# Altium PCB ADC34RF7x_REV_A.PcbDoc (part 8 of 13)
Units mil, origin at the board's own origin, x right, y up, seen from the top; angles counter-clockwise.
Board outline 6250 x 2716.54 mil, 18 copper layers (Top Layer, L2 GND, L3 PWR, L4 GND, L5 PWR/SIG, L6 GND, L7 SIGNAL, L8 GND, L9 GND, L10 SIGNAL, L11 GND, L12 SIGNAL, L13 GND, L14 PWR, L15 GND, L16 PWR/SIG, L16 GND, Bottom Layer), stack 95.314 mil thick; 668 components, 786 nets, 3150 pads, 2020 vias.
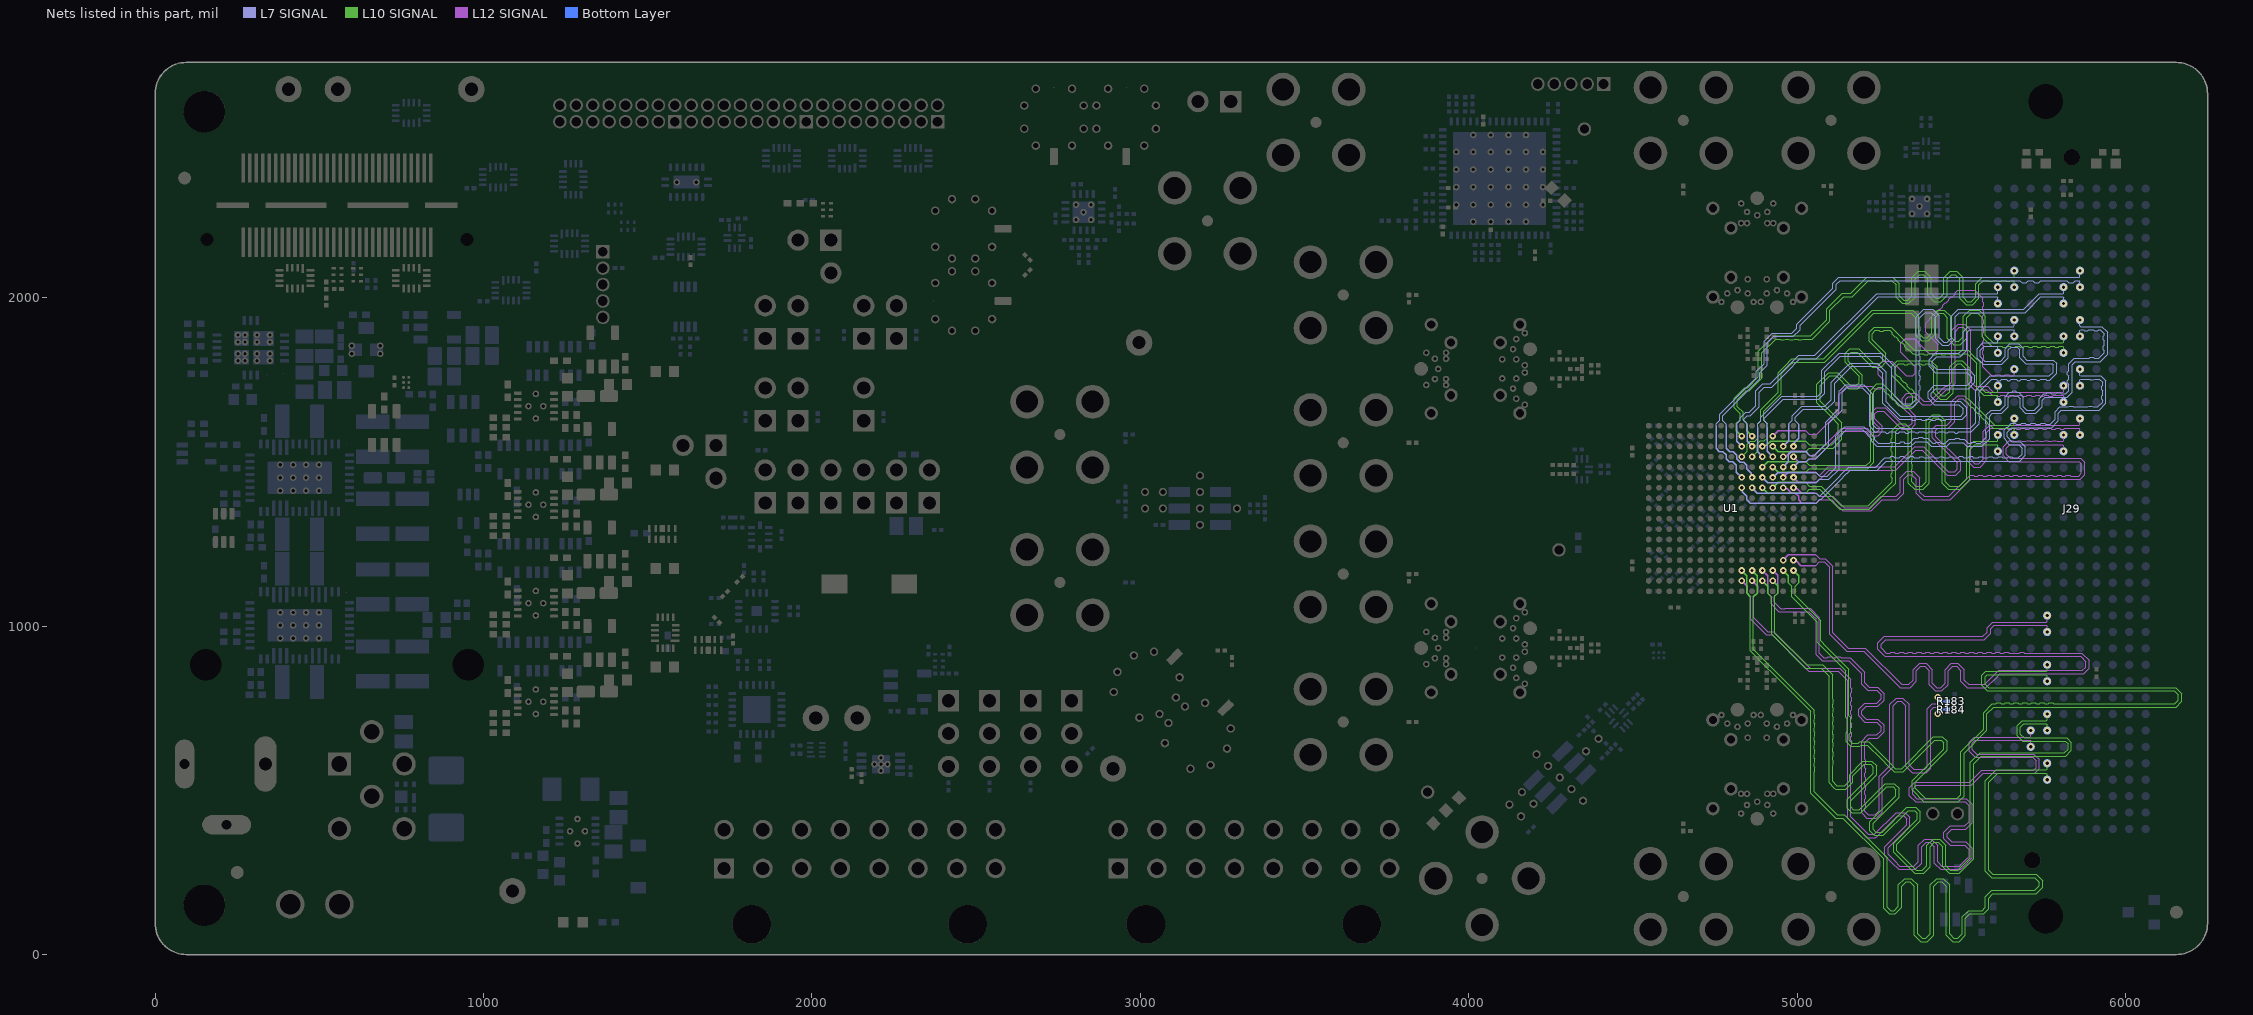
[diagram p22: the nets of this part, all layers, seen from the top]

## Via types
v1: diameter 20, hole 10, Top Layer to Bottom Layer, tented both sides, 1793 vias
v2: diameter 24, hole 12, Top Layer to Bottom Layer, tented both sides, 168 vias
v3: diameter 18, hole 8, Top Layer to Bottom Layer, tented both sides, 59 vias

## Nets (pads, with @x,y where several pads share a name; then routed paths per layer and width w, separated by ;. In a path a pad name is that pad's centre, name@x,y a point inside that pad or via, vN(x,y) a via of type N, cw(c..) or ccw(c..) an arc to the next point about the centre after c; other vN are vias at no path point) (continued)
LVDSA10_N: J29.G28 U1.C14 | length 2688
  L12 SIGNAL w3.5: 5056.71,1184.29 5068.06,1195.65 5081.98,1195.65 5099.03,1178.6 5099.03,975.58 5145.45,929.16 5151.3,923.31 5203.52,923.31 5314.56,812.27 5335.32,812.27 5344.14,812.27 5363.48,831.6 5363.48,863.69 5376.95,877.16 5388.5,877.16 5401.98,863.69 5401.98,821.92 5421.31,802.58 5441.14,802.58 5460.48,821.92 5460.48,863.69 5473.95,877.16 5485.5,877.16 5498.98,863.69 5498.98,831.6 5518.31,812.27 5564.85,812.27 5575.05,812.27 5605.9,843.13 5617.78,855 5873.13,855 5882.4,864.27 5889.08,870.95 5889.08,895.63 5867.19,917.52 5692.35,917.52 5689.77,920.1 5679.04,920.1 5676.46,917.52 5645.31,917.52 5642.73,920.1 5631.99,920.1 5629.41,917.52 5618.67,917.52 5616.09,920.1 5605.35,920.1 5602.78,917.52 5592.04,917.52 5589.46,920.1 5578.72,920.1 5576.14,917.52 5565.4,917.52 5562.82,920.1 5552.08,920.1 5549.5,917.52 5538.77,917.52 5536.19,920.1 5525.45,920.1 5522.87,917.52 5512.13,917.52 5509.55,920.1 5498.81,920.1 5496.23,917.52 5485.49,917.52 5482.91,920.1 5472.18,920.1 5469.6,917.52 5458.86,917.52 5456.28,920.1 5445.54,920.1 5442.96,917.52 5432.22,917.52 5429.64,920.1 5418.91,920.1 5416.33,917.52 5405.59,917.52 5403.01,920.1 5392.27,920.1 5389.69,917.52 5378.95,917.52 5376.37,920.1 5365.63,920.1 5363.05,917.52 5352.32,917.52 5349.74,920.1 5339,920.1 5336.42,917.52 5325.68,917.52 5323.1,920.1 5312.36,920.1 5309.78,917.52 5299.05,917.52 5296.47,920.1 5285.73,920.1 5283.15,917.52 5272.41,917.52 ; 5272.19,917.52 5256.15,933.55 5256.15,945.1 5269.63,958.58 5569.75,958.58 5589.08,977.91 5589.08,991.3 5595.45,997.68 5600.05,1002.27 5759.37,1002.27 5761.42,1000.22 v1(5761.42,982.27)
  L12 SIGNAL w4: v1(4988.98,1200.76) 4992.04,1197.7 4998.27,1197.7 5011.69,1184.29 5056.71,1184.29
LVDSA10_P: J29.G27 U1.D14 | length 2687.6
  L12 SIGNAL w3.5: 5056.95,1217 5068.3,1205.65 5086.12,1205.65 5109.03,1182.74 5109.03,979.72 5155.45,933.31 5207.66,933.31 5318.7,822.27 5335.32,822.27 5340,822.27 5353.48,835.74 5353.48,867.83 5372.81,887.16 5392.64,887.16 5411.98,867.83 5411.98,826.06 5425.45,812.58 5437,812.58 5450.48,826.06 5450.48,867.83 5469.81,887.16 5489.64,887.16 5508.98,867.83 5508.98,835.74 5522.45,822.27 5564.85,822.27 5570.9,822.27 5595.9,847.27 5613.64,865 5868.99,865 5878.26,874.27 5879.08,875.09 5879.08,891.49 5863.05,907.52 5268.05,907.52 5265.12,910.45 5246.15,929.41 5246.15,949.24 5265.49,968.58 5565.61,968.58 5579.08,982.05 5579.08,995.44 5595.9,1012.27 5759.37,1012.27 5761.42,1014.32 v1(5761.42,1032.27)
  L12 SIGNAL w4: v1(4957.48,1200.76) 4973.72,1217 5056.95,1217
LVDSA11_N: J29.G36 U1.G15 | length 3070.6
  L10 SIGNAL w3.5: 4866.98,1089.08 4866.73,1088.83 4866.73,929.01 4910.73,885.01 5051.52,744.22 5051.52,731.49 5054.1,728.91 5054.1,718.17 5051.52,715.59 5051.52,704.85 5054.1,702.27 5054.1,691.53 5051.52,688.95 5051.52,678.21 5054.1,675.63 5054.1,664.9 5051.52,662.32 5051.52,651.58 5054.1,649 5054.1,638.26 5051.52,635.68 5051.52,624.94 5054.1,622.36 5054.1,611.62 5051.52,609.04 5051.52,598.31 5054.1,595.73 5054.1,584.99 5051.52,582.41 5051.52,571.67 5054.1,569.09 5054.1,558.35 5051.52,555.77 5051.52,495.71 5121.71,425.52 5143.48,425.52 5273.93,295.07 5273.93,144.65 5284.67,133.9 5290.63,133.9 5295.31,133.9 5308.78,147.38 5308.78,212.07 5328.11,231.4 5347.95,231.4 5367.28,212.07 5367.28,62.67 5380.76,49.2 5392.31,49.2 5405.78,62.67 5405.78,212.07 5425.11,231.4 5444.95,231.4 5464.28,212.07 5464.28,62.67 5477.76,49.2 5489.31,49.2 5502.78,62.67 5502.78,114.57 5522.11,133.9 5556.49,133.9 5563.67,133.9 5573,143.23 5573,175.94 5592.33,195.27 5724.44,195.27 5737.91,208.74 5737.91,220.29 5724.44,233.77 5592.33,233.77 5573,253.1 5573,261.92 5573,529 5606.27,562.27 5759.37,562.27 5761.42,564.32 v1(5761.42,582.27)
  L10 SIGNAL w4: v1(4862.99,1169.29) 4878.51,1153.78 4878.51,1144.44 4878.49,1131.17 ; 4866.98,1089.08 4878.51,1100.6 4878.51,1131.15
LVDSA11_P: J29.G37 U1.H15 | length 3071.3
  L10 SIGNAL w3.5: 4856.48,1091.59 4856.73,1091.34 4856.73,924.87 4906.59,875.01 4922.41,859.19 4987.84,793.76 5041.52,740.08 5041.52,491.56 5117.57,415.52 5139.34,415.52 5263.93,290.93 5263.93,140.51 5280.53,123.9 5290.63,123.9 5299.45,123.9 5318.78,143.24 5318.78,207.93 5332.26,221.4 5343.81,221.4 5357.28,207.93 5357.28,58.53 5376.61,39.2 5396.45,39.2 5415.78,58.53 5415.78,207.93 5429.26,221.4 5440.81,221.4 5454.28,207.93 5454.28,58.53 5473.61,39.2 5493.45,39.2 5512.78,58.53 5512.78,110.43 5526.26,123.9 5556.49,123.9 5567.81,123.9 5583,139.09 5583,143.23 5583,171.79 5596.47,185.27 5728.58,185.27 5747.91,204.6 5747.91,224.44 5728.58,243.77 5596.47,243.77 5583,257.24 5583,261.92 5583,524.86 5610.41,552.27 5759.37,552.27 5761.42,550.22 v1(5761.42,532.27)
  L10 SIGNAL w4: v1(4831.5,1169.29) 4846.99,1153.8 4846.99,1101.09 4856.48,1091.59
LVDSA12_N: R183.2 U1.E15 | length 2135.8
  L12 SIGNAL w3.5: 4940.98,1100.09 4930.98,1090.09 4930.98,1072.11 4948.98,1054.11 4949.59,1054.11 4950.72,1052.98 4962.94,1052.98 4964.06,1054.11 5039.46,1054.11 5067.68,1025.88 5067.68,917.43 5080.82,904.29 5091.56,904.29 5094.14,906.87 5104.88,906.87 5107.46,904.29 5118.2,904.29 5120.78,906.87 5131.51,906.87 5134.09,904.29 5161.3,904.29 5203.52,862.07 5206.45,859.14 5206.45,832.27 5206.45,827.59 5219.92,814.11 5246.35,814.11 5265.68,794.78 5265.68,774.95 5246.35,755.61 5210.73,755.61 5197.25,742.14 5197.25,730.59 5210.73,717.11 5246.35,717.11 5265.68,697.78 5265.68,677.95 5246.35,658.61 5219.92,658.61 5206.45,645.14 5206.45,594.97 5209.03,592.39 5209.03,581.65 5206.45,579.07 5206.45,568.33 5209.03,565.75 5209.03,555.01 5206.45,552.43 5206.45,541.7 5209.03,539.12 5209.03,528.38 5206.45,525.8 5206.45,515.06 5209.03,512.48 5209.03,501.74 5206.45,499.16 5206.45,488.42 5209.03,485.84 5209.03,475.11 5206.45,472.53 5206.45,461.79 5209.03,459.21 5209.03,448.47 5206.45,445.89 5206.45,435.69 5216.63,425.52 5237.42,425.52 5250,438.09 5250,542.65 5264.52,557.18 5282.68,575.33 5282.68,761.49 5302.01,780.82 5321.85,780.82 5341.18,761.49 5341.18,577.34 5354.65,563.87 5361.88,563.87 5389.05,563.87 5396.37,571.19 5396.37,748 5411.6,763.24 5426,763.24 5428.05,765.29 v1(5428.05,783.24)
  L12 SIGNAL w4: v1(4925.98,1169.29) 4940.98,1154.29 4940.98,1100.09
  Bottom Layer w6.5: v1(5428.05,783.24) 5440.55,770.74 R183.2@5458.05,770.74
LVDSA12_P: R184.2 U1.F15 | length 2134.8
  L12 SIGNAL w3.5: 4910.98,1100.09 4920.98,1090.09 4920.98,1082.27 ; 4920.98,1082.03 4920.98,1067.97 4944.84,1044.11 4945.45,1044.11 4945.53,1044.03 4968.13,1044.03 4968.2,1044.11 5035.31,1044.11 5049.78,1029.64 5057.68,1021.74 5057.68,913.29 5076.68,894.29 5157.16,894.29 5196.45,855 5196.45,832.27 5196.45,823.45 5215.78,804.11 5242.2,804.11 5255.68,790.64 5255.68,779.09 5242.2,765.61 5206.58,765.61 5187.25,746.28 5187.25,726.45 5206.58,707.11 5242.2,707.11 5255.68,693.64 5255.68,682.09 5242.2,668.61 5215.78,668.61 5196.45,649.28 5196.45,594.97 5196.45,431.55 5212.48,415.52 5241.57,415.52 5260,433.95 5260,538.51 5264.52,543.04 5292.68,571.19 5292.68,757.35 5306.15,770.82 5317.7,770.82 5331.18,757.35 5331.18,573.2 5350.51,553.87 5361.88,553.87 5393.19,553.87 5406.37,567.05 5406.37,743.86 5415.75,753.24 5426,753.24 5428.05,751.19 v1(5428.05,733.24)
  L12 SIGNAL w4: v1(4894.49,1169.29) 4910.98,1152.8 4910.98,1106.3 4910.98,1100.09
  Bottom Layer w6.5: v1(5428.05,733.24) 5440.55,745.74 R184.2@5458.05,745.74
LVDSA13_N: J29.G30 U1.C15 | length 3101.8
  L10 SIGNAL w3.5: 5004.98,1132.09 4994.23,1121.34 4994.23,1093.7 5071.48,1016.45 5071.48,954.97 5087.45,939.01 5157.97,868.49 5157.97,727.14 5163.29,721.81 5163.29,675.12 5159.48,671.3 5159.48,652.24 5167.64,644.07 5186.7,644.07 5190.52,647.89 5217.86,647.89 5220.79,644.96 5286.73,579.02 5299.63,566.13 5318.68,566.13 5415.32,662.76 5442.66,662.76 5456.68,648.73 5456.68,621.39 5360.05,524.76 5360.05,505.7 5390.24,475.52 5487.23,475.52 5498.36,486.64 5498.36,616.97 5567.81,686.41 5567.81,736.73 5594.65,763.57 5605.38,763.57 5607.96,766.15 5618.7,766.15 5621.28,763.57 5632.02,763.57 5634.6,766.15 5645.34,766.15 5647.92,763.57 5658.66,763.57 5661.24,766.15 5671.97,766.15 5674.55,763.57 5685.29,763.57 5687.87,766.15 5698.61,766.15 5701.19,763.57 5711.93,763.57 5714.51,766.15 5725.24,766.15 5727.82,763.57 5738.56,763.57 5741.14,766.15 5751.88,766.15 5754.46,763.57 5765.2,763.57 5767.78,766.15 5778.52,766.15 5781.1,763.57 6149.83,763.57 6161,774.74 6161,790.51 6148.56,802.95 5579.45,802.95 5565.93,816.47 5563,819.4 5563,850.6 5574.67,862.27 5759.37,862.27 5761.42,864.32 v1(5761.42,882.27)
  L10 SIGNAL w4: v1(4988.98,1169.29) 5004.98,1153.29 5004.98,1132.09
LVDSA13_P: J29.G31 U1.D15 | length 3103.4
  L10 SIGNAL w3.5: 4973.48,1131.58 4984.23,1120.83 4984.23,1089.56 5061.48,1012.31 5061.48,950.83 5083.31,929.01 5147.97,864.35 5147.97,723 5153.29,717.67 5153.29,679.26 5149.48,675.44 5149.48,648.1 5163.5,634.07 5190.84,634.07 5194.66,637.89 5213.72,637.89 5254.25,597.36 5257.55,594.06 5276.73,574.88 5295.48,556.13 5322.82,556.13 5369.46,602.76 5419.46,652.76 5438.51,652.76 5446.68,644.59 5446.68,625.54 5396.68,575.54 5350.05,528.9 5350.05,501.56 5386.1,465.52 5491.38,465.52 5508.36,482.5 5508.36,612.82 5571.95,676.41 5577.81,682.27 5577.81,732.59 5598.79,753.57 6153.97,753.57 6171,770.6 6171,794.65 6152.7,812.95 5583.59,812.95 5573,823.54 5573,846.45 5578.81,852.27 5759.37,852.27 5761.42,850.22 v1(5761.42,832.27)
  L10 SIGNAL w4: v1(4957.48,1169.29) 4973.48,1153.29 4973.48,1131.58
LVDSA14_N: J29.H34 U1.G16 | length 3081.5
  L12 SIGNAL w3.5: 4879.49,1101.58 4868.74,1090.83 4868.74,1025.31 4910.76,983.29 4928.7,983.29 4934.56,977.43 5039.55,872.45 5129.35,872.45 5163.52,838.28 5163.52,812.27 5166.1,809.69 5166.1,798.95 5163.52,796.37 5163.52,785.63 5166.1,783.05 5166.1,772.32 5163.52,769.74 5163.52,759 5166.1,756.42 5166.1,745.68 5163.52,743.1 5163.52,732.36 5166.1,729.78 5166.1,719.04 5163.52,716.46 5163.52,705.73 5166.1,703.15 5166.1,692.41 5163.52,689.83 5163.52,679.09 5166.1,676.51 5166.1,665.77 5163.52,663.19 5163.52,652.45 5166.1,649.88 5166.1,639.14 5163.52,636.56 5163.52,418.9 5184.77,397.65 5213.32,369.1 5216.63,365.79 5235.68,365.79 5301.95,432.06 5329.29,432.06 5343.31,418.03 5343.31,390.69 5277.05,324.43 5277.05,305.37 5292.35,290.07 5295.66,286.76 5313.16,269.26 5350.98,269.26 5355.66,269.26 5369.13,282.73 5369.13,331.96 5388.46,351.3 5408.3,351.3 5427.63,331.96 5427.63,282.73 5441.11,269.26 5494.77,269.26 5500.38,274.86 5503.39,277.87 5520,294.48 5523.65,298.14 5523.65,314.81 5523.65,319.49 5510.18,332.97 5466.35,332.97 5447.02,352.3 5447.02,372.14 5466.35,391.47 5510.18,391.47 5523.65,404.94 5523.65,435.69 5523.65,452.73 5511.64,464.74 5360.91,464.74 5341.55,484.09 5341.55,507.48 5358.77,524.7 5525.86,524.7 5562.7,561.54 5719.8,561.54 5727.56,569.29 5727.56,589.73 5716.92,600.36 5542.46,600.36 5539.53,603.29 5523.65,619.17 5523.65,647.06 5538.86,662.27 5709.37,662.27 5711.42,664.32 v1(5711.42,682.27)
  L12 SIGNAL w4: v1(4862.99,1137.8) 4879.49,1121.3 4879.49,1101.58
LVDSA14_P: J29.H35 U1.H16 | length 3083.1
  L12 SIGNAL w3.5: 4847.99,1100.09 4858.74,1089.34 4858.74,1021.17 4872.42,1007.49 4906.62,973.29 4924.56,973.29 5035.41,862.45 5125.21,862.45 5153.52,834.14 5153.52,414.76 5180.63,387.65 5196.45,371.83 5206.25,362.03 5209.55,358.72 5212.48,355.79 5239.82,355.79 5306.09,422.06 5325.14,422.06 5333.31,413.89 5333.31,394.83 5267.05,328.57 5267.05,301.23 5285.28,282.99 5288.59,279.69 5309.02,259.26 5350.98,259.26 5359.8,259.26 5379.13,278.59 5379.13,327.82 5392.61,341.3 5404.16,341.3 5417.63,327.82 5417.63,278.59 5436.96,259.26 5498.92,259.26 5507.45,267.79 5518.25,278.59 5520,280.34 5533.65,293.99 5533.65,314.81 5533.65,323.64 5514.32,342.97 5470.49,342.97 5457.02,356.44 5457.02,367.99 5470.49,381.47 5514.32,381.47 5533.65,400.8 5533.65,435.69 5533.65,456.87 5515.78,474.74 5365.05,474.74 5351.55,488.23 5351.55,503.34 5362.92,514.7 5530,514.7 5566.84,551.54 5723.94,551.54 5737.56,565.15 5737.56,593.87 5723.99,607.43 5721.06,610.36 5546.6,610.36 5533.65,623.31 5533.65,642.92 5543,652.27 5709.37,652.27 5711.42,650.22 v1(5711.42,632.27)
  L12 SIGNAL w4: v1(4831.5,1137.8) 4847.99,1121.3 4847.99,1100.09
LVDSA15_N: J29.G33 U1.E16 | length 3112
  L10 SIGNAL w3.5: 4940.36,1099.46 4932.69,1091.79 4932.69,978.64 5029.06,882.27 5077.59,882.27 5108,851.86 5108,777.57 5110.58,774.99 5110.58,764.26 5108,761.68 5108,750.94 5110.58,748.36 5110.58,737.62 5108,735.04 5108,724.3 5110.58,721.72 5110.58,710.99 5108,708.41 5108,697.67 5110.58,695.09 5110.58,684.35 5108,681.77 5108,671.03 5110.58,668.45 5110.58,657.71 5108,655.13 5108,644.4 5110.58,641.82 5110.58,631.08 5108,628.5 5108,617.76 5110.58,615.18 5110.58,604.44 5108,601.86 5108,591.12 5110.58,588.55 5110.58,577.81 5108,575.23 5108,526.89 5117.92,516.98 5121.22,513.67 5144.43,513.67 5159.76,529 5159.76,544 5159.76,548.14 5200.48,588.87 5227.82,588.87 5241.85,574.84 5241.85,547.5 5162.79,468.45 5162.79,449.39 5170.96,441.22 5190.01,441.22 5269.07,520.28 5296.41,520.28 5310.43,506.25 5310.43,478.91 5231.38,399.86 5231.38,380.8 5239.55,372.63 5258.6,372.63 5334.39,448.42 5361.73,448.42 5375.75,434.39 5375.75,407.05 5303.82,335.13 5303.82,316.07 5332.8,287.09 5362.65,257.24 5376.61,257.24 5381.29,257.24 5394.77,270.72 5394.77,331.96 5414.1,351.3 5433.94,351.3 5453.27,331.96 5453.27,270.72 5466.74,257.24 5489.96,257.24 5527.79,295.07 5527.79,585 5557.02,614.24 5814.24,614.24 5825.5,625.5 5825.5,641.26 5817.08,649.68 5686.94,649.68 5685.47,651.14 5672.8,663.81 5669.88,666.74 5669.88,696.58 5685.56,712.27 5759.37,712.27 5761.42,714.32 v1(5761.42,732.27)
  L10 SIGNAL w4: v1(4925.98,1137.8) 4940.98,1122.8 4940.98,1100.09 4940.36,1099.46
LVDSA15_P: J29.G34 U1.F16 | length 3113.5
  L10 SIGNAL w3.5: 4910.49,1100.58 4922.69,1088.38 4922.69,974.5 5024.91,872.27 5073.45,872.27 5098,847.72 5098,522.75 5110.84,509.91 5113.77,506.98 5117.08,503.67 5125.28,503.67 5148.57,503.67 5169.76,524.86 5169.76,544 5204.62,578.87 5223.68,578.87 5231.85,570.7 5231.85,551.65 5152.79,472.59 5152.79,445.25 5166.81,431.22 5194.15,431.22 5273.21,510.28 5292.27,510.28 5300.43,502.11 5300.43,483.06 5221.38,404 5221.38,376.66 5235.4,362.63 5262.74,362.63 5338.53,438.42 5357.58,438.42 5365.75,430.25 5365.75,411.2 5293.82,339.27 5293.82,311.93 5319.5,286.26 5325.73,280.02 5358.51,247.24 5376.61,247.24 5385.44,247.24 5404.77,266.58 5404.77,327.82 5418.24,341.3 5429.79,341.3 5443.27,327.82 5443.27,266.58 5462.6,247.24 5489.96,247.24 5494.1,247.24 5537.79,290.93 5537.79,580.86 5561.16,604.24 5818.38,604.24 5835.5,621.36 5835.5,645.4 5821.23,659.68 5691.08,659.68 5679.88,670.88 5679.88,692.44 5689.7,702.27 5759.37,702.27 5761.42,700.22 v1(5761.42,682.27)
  L10 SIGNAL w4: v1(4894.49,1137.8) 4910.49,1121.8 4910.49,1100.58
LVDSB0_N: J29.E13 U1.G7 | length 1565.8
  L7 SIGNAL w3.5: 5051.97,1405 5057.59,1405 5066.79,1395.81 5069.68,1395.81 5131.14,1457.26 5131.14,1458.68 5147.41,1474.94 5148.82,1474.94 5158.02,1484.14 5239.45,1484.14 5267.51,1512.2 5281.57,1512.2 5286.17,1516.8 5292.88,1516.8 5297.47,1512.2 5311.53,1512.2 5316.13,1516.8 5322.83,1516.8 5327.43,1512.2 5341.49,1512.2 5346.16,1516.87 5352.72,1516.87 5357.39,1512.2 5371.45,1512.2 5375.53,1516.29 5383.26,1516.29 5387.34,1512.2 5401.4,1512.2 5405.71,1516.5 5413,1516.5 5417.3,1512.2 5431.36,1512.2 5435.3,1516.14 5443.32,1516.14 5447.26,1512.2 5461.32,1512.2 5465.55,1516.43 5472.99,1516.43 5477.22,1512.2 5491.28,1512.2 5496.02,1516.94 5502.43,1516.94 5507.17,1512.2 5521.23,1512.2 5525.61,1516.58 5532.76,1516.58 5537.13,1512.2 5551.19,1512.2 5555.42,1516.43 5562.86,1516.43 5567.09,1512.2 5581.15,1512.2 5584.64,1515.69 5593.56,1515.69 5597.05,1512.2 5611.11,1512.2 5614.84,1515.93 5623.27,1515.93 5627,1512.2 5641.06,1512.2 5644.91,1516.05 5653.11,1516.05 5656.96,1512.2 5673.46,1512.2 5685,1523.74 5685,1542.31 5675.26,1552.05 5646.49,1552.05 5638.89,1559.64 5638.89,1563.29 5630.19,1571.99 5630.19,1598.55 5637.78,1606.15 5641.43,1606.15 5652.44,1617.15 5664.16,1617.15 5666.74,1614.57 5680.8,1614.57 5683.38,1617.15 5694.11,1617.15 5696.69,1614.57 5710.75,1614.57 5713.33,1617.15 5724.07,1617.15 5726.65,1614.57 5740.71,1614.57 5743.29,1617.15 5754.03,1617.15 5756.61,1614.57 5770.67,1614.57 5785.42,1629.33 5785.42,1652.7 5800.24,1667.52 5825.67,1667.52 5828.25,1670.1 5838.99,1670.1 5841.57,1667.52 5885.58,1667.52 5888.16,1670.1 5898.9,1670.1 5901.48,1667.52 5915.54,1667.52 5930.29,1682.27 5930.29,1687.51 5927.71,1690.09 5927.71,1700.83 5930.29,1703.41 5930.29,1717.47 5927.71,1720.05 5927.71,1730.78 5930.29,1733.36 5930.29,1742.42 5928.75,1743.96 5920.44,1752.27 5906.39,1752.27 5903.81,1749.69 5893.07,1749.69 5890.49,1752.27 5863.47,1752.27 5861.42,1750.22 v1(5861.42,1732.27)
  L7 SIGNAL w4: v1(4862.99,1421.26) 4879.25,1405 5051.97,1405
LVDSB0_P: J29.E12 U1.H7 | length 1587.2
  L7 SIGNAL w3.5: 5051.97,1374.76 5057.83,1374.76 5068.87,1385.81 5073.83,1385.81 5141.14,1453.12 5141.14,1454.54 5151.55,1464.94 5152.96,1464.94 5162.16,1474.14 5243.59,1474.14 5271.66,1502.2 5677.6,1502.2 5695,1519.6 5695,1546.45 5679.4,1562.05 5654.28,1562.05 5640.19,1576.14 5640.19,1590.76 5654,1604.57 5774.81,1604.57 5795.42,1625.19 5795.42,1648.56 5804.38,1657.52 5871.67,1657.52 5919.68,1657.52 5940.29,1678.13 5940.29,1746.57 5935.82,1751.03 5924.59,1762.27 5863.47,1762.27 5861.42,1764.32 v1(5861.42,1782.27)
  L7 SIGNAL w4: v1(4831.5,1421.26) 4833.67,1419.09 4833.67,1408.8 4847.24,1395.23 4847.24,1384.3 4856.78,1374.76 5051.97,1374.76
LVDSB1_N: J29.K16 U1.E7 | length 1631.9
  L10 SIGNAL w3.5: 5025.92,1437.52 5037.18,1426.26 5073.85,1426.26 5134.07,1366.05 5216.3,1366.05 5289.99,1439.73 5289.99,1450.47 5287.41,1453.05 5287.41,1463.79 5289.99,1466.37 5289.99,1477.11 5287.41,1479.69 5287.41,1490.43 5289.99,1493.01 5289.99,1503.74 5287.41,1506.32 5287.41,1517.06 5289.99,1519.64 5289.99,1530.38 5287.41,1532.96 5287.41,1543.7 5289.99,1546.28 5289.99,1557.01 5287.41,1559.59 5287.41,1570.33 5289.99,1572.91 5289.99,1596.93 5309.32,1616.26 5329.15,1616.26 5348.49,1596.93 5348.49,1519.64 5351.07,1517.06 5351.07,1506.32 5348.49,1503.74 5348.49,1493.01 5351.07,1490.43 5351.07,1479.69 5348.49,1477.11 5348.49,1466.37 5351.07,1463.79 5351.07,1453.05 5348.49,1450.47 5348.49,1439.73 5361.96,1426.26 5374.89,1426.26 5379.57,1426.26 5393.05,1439.73 5393.05,1624.86 5412.38,1644.2 5432.21,1644.2 5451.55,1624.86 5451.55,1439.73 5465.02,1426.26 5475.15,1426.26 5493.4,1426.26 5516.36,1449.22 5516.36,1541.38 5537.24,1562.27 5609.37,1562.27 5611.42,1564.32 v1(5611.42,1582.27)
  L10 SIGNAL w4: v1(4925.98,1421.26) 4942.24,1437.52 5025.92,1437.52
LVDSB1_P: J29.K17 U1.F7 | length 1646.3
  L10 SIGNAL w3.5: 5025.92,1405 5037.18,1416.26 5069.71,1416.26 5122.7,1363.27 5129.92,1356.05 5220.44,1356.05 5280.65,1416.26 5299.99,1435.59 5299.99,1592.78 5313.46,1606.26 5325.01,1606.26 5338.49,1592.78 5338.49,1435.59 5357.82,1416.26 5374.89,1416.26 5383.71,1416.26 5403.05,1435.59 5403.05,1620.72 5416.52,1634.2 5428.07,1634.2 5441.55,1620.72 5441.55,1435.59 5460.88,1416.26 5475.15,1416.26 5497.54,1416.26 5526.36,1445.08 5526.36,1537.24 5541.39,1552.27 5609.37,1552.27 5611.42,1550.22 v1(5611.42,1532.27)
  L10 SIGNAL w4: v1(4894.49,1421.26) 4910.75,1405 5025.92,1405
LVDSB2_N: J29.F16 U1.C7 | length 1612.4
  L12 SIGNAL w3.5: 5057.95,1405 5068.06,1394.88 5109.09,1394.88 5142.92,1361.06 5221.98,1361.06 5231.11,1370.19 5255.81,1394.88 5301.34,1394.88 5314.82,1408.36 5314.82,1451.53 5334.15,1470.86 5353.99,1470.86 5373.32,1451.53 5373.32,1408.36 5386.79,1394.88 5392.15,1394.88 5461.97,1394.88 5526.68,1459.6 5537.42,1459.6 5540,1457.02 5550.74,1457.02 5553.32,1459.6 5564.06,1459.6 5566.64,1457.02 5577.38,1457.02 5579.96,1459.6 5590.69,1459.6 5593.27,1457.02 5604.01,1457.02 5606.59,1459.6 5617.33,1459.6 5619.91,1457.02 5630.65,1457.02 5633.23,1459.6 5643.96,1459.6 5646.54,1457.02 5657.28,1457.02 5659.86,1459.6 5670.6,1459.6 5673.18,1457.02 5683.92,1457.02 5686.5,1459.6 5697.24,1459.6 5699.82,1457.02 5710.55,1457.02 5713.13,1459.6 5723.87,1459.6 5726.45,1457.02 5737.19,1457.02 5739.77,1459.6 5750.51,1459.6 5753.09,1457.02 5763.82,1457.02 5766.4,1459.6 5777.14,1459.6 5779.72,1457.02 5790.46,1457.02 5793.04,1459.6 5803.78,1459.6 5806.36,1457.02 5817.1,1457.02 5819.68,1459.6 5830.41,1459.6 5832.99,1457.02 5858.13,1457.02 5865.93,1464.82 5865.93,1494.19 5859.37,1500.75 5645.22,1500.75 5630.17,1515.79 5627.24,1518.72 5627.24,1546.53 5645.57,1564.85 5656.3,1564.85 5658.88,1562.27 5669.62,1562.27 5672.2,1564.85 5682.94,1564.85 5685.52,1562.27 5696.26,1562.27 5698.84,1564.85 5709.57,1564.85 5712.15,1562.27 5722.89,1562.27 5725.47,1564.85 5736.21,1564.85 5738.79,1562.27 5749.53,1562.27 5752.11,1564.85 5762.85,1564.85 5765.43,1562.27 5776.16,1562.27 5778.74,1564.85 5789.48,1564.85 5792.06,1562.27 5809.37,1562.27 5811.42,1564.32 v1(5811.42,1582.27)
  L12 SIGNAL w4: v1(4988.98,1421.26) 4991.53,1418.71 5001.05,1418.71 5014.76,1405 5057.95,1405
LVDSB2_P: J29.F17 U1.D7 | length 1624.5
  L12 SIGNAL w3.5: 5058.18,1374.76 5068.3,1384.88 5104.95,1384.88 5118.14,1371.69 5135.84,1353.99 5138.77,1351.06 5226.13,1351.06 5241.11,1366.05 5259.95,1384.88 5305.49,1384.88 5324.82,1404.21 5324.82,1447.38 5338.29,1460.86 5349.84,1460.86 5363.32,1447.38 5363.32,1404.21 5382.65,1384.88 5392.15,1384.88 5466.11,1384.88 5528.25,1447.02 5862.27,1447.02 5875.93,1460.67 5875.93,1498.33 5866.44,1507.82 5863.51,1510.75 5649.36,1510.75 5637.24,1522.86 5637.24,1542.38 5647.13,1552.27 5809.37,1552.27 5811.42,1550.22 v1(5811.42,1532.27)
  L12 SIGNAL w4: v1(4957.48,1421.26) 4960.23,1418.51 4969.36,1418.51 4972.98,1414.89 4972.98,1414.63 4982.35,1405.26 4994.69,1405.26 5004.48,1395.48 5004.48,1384.55 5014.26,1374.76 5058.18,1374.76
LVDSB3_N: J29.E7 U1.G6 | length 1595.6
  L7 SIGNAL w3.5: 4785,1610.9 4785,1614.6 4774.25,1625.35 4774.25,1640.55 4886.26,1752.56 4886.26,1771.37 4909.52,1794.62 4909.52,1862.92 4928.87,1882.27 4988.29,1882.27 5009.14,1903.12 5009.14,1915.54 5119.02,2025.42 5119.02,2040.31 5130.98,2052.27 5678.73,2052.27 5685,2046 5698,2046 5704,2052 5717,2052 5723.27,2045.73 5736.27,2045.73 5742.27,2051.73 5821.64,2051.73 5827.37,2046 5840.37,2046 5846.37,2052 5859.37,2052 5861.42,2049.95 v1(5861.42,2032.27)
  L7 SIGNAL w4: 4785,1610.9 4785,1541.03 4795.19,1530.84 4806.12,1530.84 4816.31,1520.65 4816.31,1509.72 4826.4,1499.63 4837.34,1499.63 4847.24,1489.72 4847.24,1478.79 4860.82,1465.21 4860.82,1454.93 v1(4862.99,1452.76)
LVDSB3_P: J29.E6 U1.H6 | length 1597.5
  L7 SIGNAL w3.5: 4753.5,1610.24 4753.5,1616.1 4764.25,1626.84 4764.25,1640.55 4764.25,1644.7 4876.26,1756.7 4876.26,1775.51 4899.52,1798.76 4899.52,1867.06 4924.72,1892.27 4984.15,1892.27 4999.14,1907.26 4999.14,1919.68 5109.02,2029.56 5109.02,2044.45 5126.83,2062.27 5859.37,2062.27 5861.42,2064.32 v1(5861.42,2082.27)
  L7 SIGNAL w4: 4753.5,1610.24 4753.5,1545.29 4753.54,1545.25 4753.54,1540.99 4763.43,1531.1 4774.36,1531.1 4784.25,1521.21 4784.25,1510.28 4793.79,1500.75 4804.72,1500.75 4815,1490.46 4815,1469.25 v1(4831.5,1452.76)
LVDSB4_N: J29.E10 U1.E6 | length 1682.9
  L7 SIGNAL w3.5: 5058.29,1467.65 5068.93,1457.01 5092.5,1457.01 5117.76,1482.27 5117.76,1579.64 5145.36,1607.24 5203.35,1607.24 5219.4,1591.18 5236.86,1573.72 5236.86,1567.64 5247.25,1557.25 5282.71,1557.25 5285.77,1560.32 5295.55,1560.32 5298.61,1557.25 5312.67,1557.25 5316.17,1560.76 5325.06,1560.76 5328.57,1557.25 5342.55,1557.25 ; 5342.63,1557.25 5342.55,1557.25 ; 5398.45,1571.84 5398.38,1571.84 ; 5451.17,1557.25 5451.09,1557.25 ; 5509.8,1569.03 5509.73,1569.03 ; 5558.9,1557.25 5558.83,1557.25 ; 5576.42,1643.54 5576.42,1643.47 ; 5818.32,1707.02 5818.24,1707.02 ; 5827.37,1716.07 5827.37,1716.14 ; v1(5861.42,1882.27) 5861.42,1900.22 5863.47,1902.27 5872.45,1902.27 5875.03,1899.69 5885.77,1899.69 5888.35,1902.27 5902.41,1902.27 5904.99,1899.69 5915.73,1899.69 5918.31,1902.27 5923.68,1902.27 5926.61,1899.34 5933.68,1892.27 5935.34,1890.61 5935.34,1885.11 5932.76,1882.53 5932.76,1871.79 5935.34,1869.21 5935.34,1855.15 5932.76,1852.57 5932.76,1841.83 5935.34,1839.25 5935.34,1832.27 5918.82,1815.75 ; 5918.9,1815.75 5918.82,1815.75 ; 5342.55,1557.25 5357.13,1571.84 5368.5,1571.84 5371.9,1575.24 5380.99,1575.24 5384.39,1571.84 5398.38,1571.84 ; 5398.38,1571.84 5412.96,1557.25 5421.21,1557.25 5423.79,1559.83 5434.53,1559.83 5437.11,1557.25 5451.09,1557.25 ; 5451.09,1557.25 5462.86,1569.03 5479.84,1569.03 5483.31,1572.5 5492.27,1572.5 5495.74,1569.03 5509.73,1569.03 ; 5509.73,1569.03 5521.5,1557.25 5528.95,1557.25 5532.16,1560.47 5541.63,1560.47 5544.84,1557.25 5558.83,1557.25 ; 5558.83,1557.25 5576.42,1574.84 5576.42,1583.63 5573.84,1586.21 5573.84,1596.95 5576.42,1599.53 5576.42,1613.59 5573.84,1616.17 5573.84,1626.9 5576.42,1629.48 5576.42,1643.47 ; 5576.42,1643.47 5590.59,1657.64 5619.18,1657.64 5633.46,1671.92 5633.46,1699 5645.93,1711.47 5652.92,1711.47 5657.58,1716.13 5664.15,1716.13 5668.81,1711.47 5674.57,1711.47 5688.85,1697.18 5688.85,1668.34 5699.55,1657.64 5722.39,1657.64 5736.67,1671.92 5736.67,1692.52 5751.17,1707.02 5758.41,1707.02 5762.36,1710.97 5770.35,1710.97 5774.3,1707.02 5788.36,1707.02 5792.09,1710.75 5800.53,1710.75 5804.26,1707.02 5818.24,1707.02 ; 5818.24,1707.02 5827.37,1716.14 ; 5827.37,1716.14 5827.37,1736.13 5826.17,1737.33 5826.17,1738.38 5823.26,1741.28 5823.26,1747.92 5827.37,1752.02 5827.37,1762.08 5823.26,1766.19 5823.26,1773.25 5826.17,1776.16 5826.17,1776.78 5827.37,1777.98 5827.37,1799.57 5843.55,1815.75 5888.94,1815.75 5892.23,1819.05 5901.55,1819.05 5904.84,1815.75 5918.82,1815.75
  L7 SIGNAL w4: v1(4925.98,1452.76) 4940.98,1467.76 5058.18,1467.76 5058.29,1467.65
LVDSB4_P: J29.E9 U1.F6 | length 1699.1
  L7 SIGNAL w3.5: 5058.18,1436.26 5068.93,1447.01 5096.64,1447.01 5127.76,1478.13 5127.76,1575.5 5149.5,1597.24 5199.21,1597.24 5226.86,1569.58 5226.86,1563.5 5243.11,1547.25 5346.69,1547.25 5361.27,1561.84 5394.23,1561.84 5408.82,1547.25 5455.23,1547.25 5467,1559.03 5505.58,1559.03 5517.36,1547.25 5562.97,1547.25 5586.42,1570.7 5586.42,1639.33 5594.73,1647.64 5623.32,1647.64 5643.46,1667.78 5643.46,1694.86 5650.07,1701.47 5670.43,1701.47 5678.85,1693.04 5678.85,1664.19 5695.41,1647.64 5726.53,1647.64 5746.67,1667.78 5746.67,1688.38 5755.31,1697.02 5822.39,1697.02 5837.37,1712 5837.37,1795.43 5847.69,1805.75 5922.97,1805.75 5945.34,1828.13 5945.34,1894.76 5940.75,1899.34 5927.82,1912.27 5901.96,1912.27 5863.47,1912.27 5861.42,1914.32 v1(5861.42,1932.27)
  L7 SIGNAL w4: v1(4894.49,1452.76) 4911.23,1436.01 4919.52,1436.01 4919.77,1436.26 5058.18,1436.26
LVDSB5_N: J29.E16 U1.C6 | length 1581.6
  L12 SIGNAL w3.5: 5058.18,1437.76 5068.68,1448.26 5071.82,1448.26 5098.34,1474.77 5300.85,1474.77 5357.33,1531.25 5361.77,1535.7 5380.83,1535.7 5456.52,1460 5483.86,1460 5497.89,1474.03 5497.89,1501.37 5422.2,1577.06 5422.2,1596.12 5425.51,1599.43 5428.35,1602.27 5445.47,1602.27 5460.41,1602.27 5479.75,1621.6 5479.75,1678.49 5493.22,1691.96 5504.77,1691.96 5518.25,1678.49 5518.25,1503.63 5537.58,1484.3 5557.41,1484.3 5576.75,1503.63 5576.75,1588.79 5590.22,1602.27 5594.9,1602.27 5612.98,1602.27 5615.56,1599.69 5626.3,1599.69 5628.88,1602.27 5639.62,1602.27 5642.2,1599.69 5652.94,1599.69 5655.52,1602.27 5666.25,1602.27 5668.83,1599.69 5679.57,1599.69 5682.15,1602.27 5692.89,1602.27 5695.47,1599.69 5706.21,1599.69 5708.79,1602.27 5719.52,1602.27 5722.1,1599.69 5732.84,1599.69 5735.42,1602.27 5746.16,1602.27 5748.74,1599.69 5759.48,1599.69 5762.06,1602.27 5772.8,1602.27 5775.38,1599.69 5786.11,1599.69 5788.69,1602.27 5799.43,1602.27 5802.01,1599.69 5812.75,1599.69 5815.33,1602.27 5859.37,1602.27 5861.42,1600.22 v1(5861.42,1582.27)
  L12 SIGNAL w4: v1(4988.98,1452.76) 5003.98,1437.76 5058.18,1437.76
LVDSB5_P: J29.E15 U1.D6 | length 1596.5
  L12 SIGNAL w3.5: 5057.18,1468.76 5067.68,1458.26 5094.2,1484.77 5296.71,1484.77 5350.26,1538.32 5357.63,1545.7 5384.97,1545.7 5460.67,1470 5479.72,1470 5487.89,1478.17 5487.89,1497.23 5412.2,1572.92 5412.2,1600.26 5418.44,1606.5 5424.2,1612.27 5445.47,1612.27 5456.27,1612.27 5469.75,1625.74 5469.75,1682.63 5489.08,1701.96 5508.91,1701.96 5528.25,1682.63 5528.25,1507.77 5541.72,1494.3 5553.27,1494.3 5566.75,1507.77 5566.75,1592.94 5586.08,1612.27 5594.9,1612.27 5859.37,1612.27 5861.42,1614.32 v1(5861.42,1632.27)
  L12 SIGNAL w4: v1(4957.48,1452.76) 4973.48,1468.76 5057.18,1468.76
LVDSB6_N: J29.J16 U1.E5 | length 1575.1
  L10 SIGNAL w3.5: 5026.18,1468.25 5037.18,1479.25 5214.56,1479.25 5233.68,1498.37 5233.68,1713.71 5247.33,1727.36 5256.86,1727.36 ; 5257.17,1727.05 5264.76,1719.45 5264.76,1715.8 5272.35,1708.21 5276,1708.21 5283.59,1700.62 5283.59,1696.97 5291.19,1689.38 5294.84,1689.38 5302.43,1681.78 5302.43,1678.14 5310.02,1670.54 5313.67,1670.54 5321.26,1662.95 5348.6,1662.95 5362.63,1676.98 5362.63,1704.32 ; 5362.32,1704.63 5354.72,1712.22 5354.72,1715.87 5347.13,1723.46 5343.48,1723.46 5335.89,1731.05 5335.89,1734.7 5328.3,1742.3 5324.65,1742.3 5317.06,1749.89 5317.06,1753.54 5309.46,1761.13 5305.81,1761.13 5298.22,1768.72 5298.22,1787.78 5309.21,1798.77 5323.27,1798.77 5325.85,1796.19 5336.59,1796.19 5339.17,1798.77 5349.91,1798.77 5352.49,1796.19 5363.22,1796.19 5365.8,1798.77 5376.54,1798.77 5379.12,1796.19 5389.86,1796.19 5392.44,1798.77 5403.18,1798.77 5416.65,1785.29 5416.65,1710.11 5435.99,1690.77 5455.82,1690.77 5475.15,1710.11 5475.15,1785.29 5488.63,1798.77 5498.18,1798.77 5514.68,1782.27 5514.68,1685.62 ; 5515.1,1685.2 5522.69,1677.61 5522.69,1673.96 5530.28,1666.36 5533.93,1666.36 5541.52,1658.77 5541.52,1655.12 5549.12,1647.53 5552.76,1647.53 5560.36,1639.94 5560.36,1636.29 5567.95,1628.7 5571.6,1628.7 5579.19,1621.1 5579.19,1617.45 5586.78,1609.86 5590.43,1609.86 5598.03,1602.27 5659.37,1602.27 5661.42,1600.22 v1(5661.42,1582.27)
  L10 SIGNAL w4: v1(4925.98,1484.25) 4941.98,1468.25 5026.18,1468.25
LVDSB6_P: J29.J15 U1.F5 | length 1580.3
  L10 SIGNAL w3.5: 5026.18,1500.25 5037.18,1489.25 5210.42,1489.25 5223.68,1502.51 5223.68,1717.85 5243.19,1737.36 5261,1737.36 5325.4,1672.95 5344.46,1672.95 5352.63,1681.12 5352.63,1700.17 5288.22,1764.58 5288.22,1791.92 5294.46,1798.16 5305.07,1808.77 5407.32,1808.77 5426.65,1789.44 5426.65,1714.25 5440.13,1700.77 5451.68,1700.77 5465.15,1714.25 5465.15,1789.44 5484.49,1808.77 5502.32,1808.77 5521.75,1789.34 5524.68,1786.41 5524.68,1689.76 5602.17,1612.27 5659.37,1612.27 5661.42,1614.32 v1(5661.42,1632.27)
  L10 SIGNAL w4: v1(4894.49,1484.25) 4910.49,1500.25 5026.18,1500.25
LVDSB7_N: J29.K11 U1.C5 | length 1710
  L7 SIGNAL w3.5: 5027.18,1500 5036.39,1509.21 5056.82,1509.21 5069.7,1522.09 5096.71,1549.1 5096.71,1617.04 5135.84,1656.16 5135.84,1656.69 5138.02,1658.87 5138.02,1712.01 5151.17,1725.16 5198.41,1725.16 5220.98,1702.59 5220.98,1608.7 5237.21,1592.46 5266.86,1592.46 5271.45,1587.87 5278.16,1587.87 5282.76,1592.46 5296.82,1592.46 5301.41,1587.87 5308.12,1587.87 5312.71,1592.46 5326.77,1592.46 5331.44,1587.8 5338,1587.8 5342.67,1592.46 5356.73,1592.46 5360.81,1588.38 5368.55,1588.38 5372.63,1592.46 5386.69,1592.46 5390.99,1588.16 5398.28,1588.16 5402.59,1592.46 5416.64,1592.46 5420.58,1588.53 5428.61,1588.53 5432.54,1592.46 5446.6,1592.46 5450.83,1588.24 5458.27,1588.24 5462.5,1592.46 5476.56,1592.46 5481.3,1587.72 5487.72,1587.72 5492.46,1592.46 5530.81,1592.46 5554.07,1615.72 5554.07,1623.81 5556.65,1626.39 5556.65,1637.13 5554.07,1639.71 5554.07,1653.77 5556.65,1656.35 5556.65,1667.09 5554.07,1669.67 5554.07,1683.73 5556.65,1686.31 5556.65,1697.05 5554.07,1699.62 5554.07,1713.68 5592.65,1752.27 5606.71,1752.27 5611.31,1747.67 5618.02,1747.67 5622.61,1752.27 5636.67,1752.27 5641.26,1747.67 5647.97,1747.67 5652.57,1752.27 5666.63,1752.27 5671.3,1747.6 5677.86,1747.6 5682.53,1752.27 5696.59,1752.27 5700.67,1748.19 5708.4,1748.19 5712.48,1752.27 5726.54,1752.27 5730.84,1747.97 5738.14,1747.97 5742.44,1752.27 5756.5,1752.27 5760.44,1748.33 5768.77,1748.33 5790.11,1769.67 5790.11,1799.85 5780.37,1809.58 5699.95,1809.58 5687.93,1821.6 5687.93,1845.9 5674.25,1859.58 5647.98,1859.58 5633.64,1845.24 5633.64,1821.16 5619.5,1807.02 5571.21,1807.02 5557.86,1820.37 5557.86,1839.97 5570.16,1852.27 5609.37,1852.27 5611.42,1850.22 v1(5611.42,1832.27)
  L7 SIGNAL w4: v1(4988.98,1484.25) 5004.72,1500 5027.18,1500
LVDSB7_P: J29.K10 U1.D5 | length 1710.2
  L7 SIGNAL w3.5: 5032.95,1524.98 5038.72,1519.21 5052.68,1519.21 5059.7,1526.23 5086.71,1553.24 5086.71,1621.18 5128.39,1662.86 5128.39,1716 5131.21,1718.82 5141.43,1729.04 5141.43,1729.3 5147.29,1735.16 5202.55,1735.16 5230.98,1706.74 5230.98,1612.84 5241.35,1602.46 5526.67,1602.46 5544.07,1619.86 5544.07,1717.83 5588.51,1762.27 5768.56,1762.27 5780.11,1773.81 5780.11,1795.71 5776.23,1799.58 5695.81,1799.58 5677.93,1817.46 5677.93,1841.76 5670.11,1849.58 5652.12,1849.58 5643.64,1841.1 5643.64,1817.02 5623.64,1797.02 5567.07,1797.02 5547.86,1816.22 5547.86,1844.11 5566.02,1862.27 5609.37,1862.27 5611.42,1864.32 v1(5611.42,1882.27)
  L7 SIGNAL w4: v1(4957.48,1484.25) 4973.12,1499.89 4973.12,1521.1 4982.76,1530.75 5027.18,1530.75 5032.95,1524.98
LVDSB8_N: J29.F11 U1.G4 | length 1631.7
  L10 SIGNAL w3.5: v1(4862.99,1515.75) 4878.76,1531.52 4878.76,1540.69 ; 4878.74,1540.72 4878.74,1553.77 4878.76,1555.21 4887.55,1563.99 4888.37,1563.99 ; 4888.38,1563.99 4900.6,1563.99 4909.24,1572.63 4909.24,1616.35 4898.99,1626.6 4898.99,1654.15 4952.48,1707.64 4952.48,1768.04 4975.15,1790.71 4988.37,1803.92 5084.58,1803.92 5232.92,1952.27 5246.15,1952.27 5347.38,1952.27 5360.86,1938.79 5360.86,1887.6 5380.19,1868.26 5400.03,1868.26 5419.36,1887.6 5419.36,1939.14 5432.83,1952.61 5444.38,1952.61 5457.86,1939.14 5457.86,1876.72 5477.19,1857.38 5497.03,1857.38 5516.36,1876.72 5516.36,1938.79 5529.83,1952.27 5534.51,1952.27 5550.8,1952.27 5561.14,1941.92 5563.18,1939.89 5563.18,1881.63 5569.04,1875.78 5586.69,1858.13 5592.54,1852.27 5622.92,1852.27 5625.5,1849.69 5636.24,1849.69 5638.82,1852.27 5649.55,1852.27 5652.13,1849.69 5662.87,1849.69 5665.45,1852.27 5676.19,1852.27 5678.77,1849.69 5689.51,1849.69 5692.09,1852.27 5702.83,1852.27 5705.41,1849.69 5716.14,1849.69 5718.72,1852.27 5729.46,1852.27 5732.04,1849.69 5742.78,1849.69 5745.36,1852.27 5756.1,1852.27 5758.68,1849.69 5769.41,1849.69 5771.99,1852.27 5782.73,1852.27 5785.31,1849.69 5796.05,1849.69 5798.63,1852.27 5809.37,1852.27 5811.42,1850.22 v1(5811.42,1832.27)
LVDSB8_P: J29.F10 U1.H4 | length 1633.7
  L10 SIGNAL w3.5: v1(4831.5,1515.75) 4848.24,1532.49 4848.24,1553.35 4857.65,1562.76 4870.7,1562.76 4879.74,1571.8 4879.74,1616.35 4888.99,1625.6 4888.99,1658.29 4903.68,1672.98 4908.31,1677.61 4942.48,1711.78 4942.48,1772.18 4965.15,1794.85 4984.22,1813.92 5080.43,1813.92 5228.78,1962.27 5246.15,1962.27 5351.53,1962.27 5370.86,1942.94 5370.86,1891.74 5384.33,1878.26 5395.88,1878.26 5409.36,1891.74 5409.36,1943.28 5428.69,1962.61 5448.53,1962.61 5467.86,1943.28 5467.86,1880.86 5481.33,1867.38 5492.88,1867.38 5506.36,1880.86 5506.36,1942.94 5525.69,1962.27 5534.51,1962.27 5554.94,1962.27 5568.21,1948.99 5573.18,1944.03 5573.18,1885.78 5596.69,1862.27 5809.37,1862.27 5811.42,1864.32 v1(5811.42,1882.27)
LVDSB9_N: J29.F8 U1.E4 | length 1753.4
  L7 SIGNAL w3.5: 4909.54,1605.2 4909.54,1616.04 4899.52,1626.07 4899.52,1632.27 4944.04,1676.79 4957.66,1690.41 4959.78,1690.41 4960.12,1690.75 4972.58,1690.75 4972.75,1690.58 5066.27,1690.58 5069.02,1693.34 5069.51,1693.34 5084.87,1708.7 5084.87,1774.58 5131.89,1821.6 5251.43,1821.6 5280.32,1792.7 5288.46,1784.56 5288.46,1696.24 5317.18,1667.52 5353.99,1667.52 5372.65,1686.17 5372.65,1717.93 5375.23,1720.51 5375.23,1731.25 5372.65,1733.83 5372.65,1747.89 5375.23,1750.47 5375.23,1761.21 5372.65,1763.79 5372.65,1777.85 5375.23,1780.43 5375.23,1791.17 5372.65,1793.74 5372.65,1807.8 5375.23,1810.38 5375.23,1821.12 5372.65,1823.7 5372.65,1837.76 5375.23,1840.34 5375.23,1851.08 5372.65,1853.66 5372.65,1867.72 5375.23,1870.3 5375.23,1881.04 5372.65,1883.62 5372.65,1897.68 5375.23,1900.26 5375.23,1910.99 5372.65,1913.57 5372.65,1937.68 5386.43,1951.46 5389.96,1955 5409,1955 5422.47,1941.53 5422.47,1874.36 5441.8,1855.03 5461.64,1855.03 5480.97,1874.36 5480.97,1941.53 5494.45,1955 5499.13,1955 5695,1955 5742.27,2002.27 5809.37,2002.27 5811.42,2000.22 v1(5811.42,1982.27)
  L7 SIGNAL w4: 4909.54,1605.2 4909.54,1532.19 v1(4925.98,1515.75)
LVDSB9_P: J29.F7 U1.F4 | length 1754.4
  L7 SIGNAL w3.5: 4879.49,1605.2 4879.49,1616.1 4889.52,1626.12 4889.52,1636.41 4934.04,1680.93 4953.51,1700.41 4976.58,1700.41 4976.75,1700.24 5062.26,1700.24 5074.87,1712.84 5074.87,1778.72 5127.75,1831.6 5255.57,1831.6 5287.39,1799.77 5298.46,1788.71 5298.46,1700.38 5321.33,1677.52 5349.85,1677.52 5362.65,1690.31 5362.65,1941.82 5385.82,1965 5386.43,1965 5413.14,1965 5432.47,1945.67 5432.47,1878.5 5445.95,1865.03 5457.5,1865.03 5470.97,1878.5 5470.97,1945.67 5490.3,1965 5499.13,1965 5690.86,1965 5738.13,2012.27 5809.37,2012.27 5811.42,2014.32 v1(5811.42,2032.27)
  L7 SIGNAL w4: 4879.49,1605.2 4879.49,1530.75 v1(4894.49,1515.75)
LVDSB10_N: J29.F14 U1.C4 | length 1528.5
  L12 SIGNAL w3.5: 5027.18,1500.75 5036.69,1510.25 5057.11,1510.25 5130.78,1583.92 5139.79,1592.94 5209.94,1592.94 5219.92,1582.95 5222.85,1580.02 5246.71,1580.02 5259.9,1593.21 5259.9,1609.23 5237.09,1632.04 5237.09,1646.26 5245.26,1654.43 5264.31,1654.43 5318.81,1599.93 5346.15,1599.93 5360.18,1613.95 5360.18,1641.29 5330.24,1671.23 5330.24,1690.29 5338.41,1698.46 5357.46,1698.46 5381.85,1674.07 5409.19,1674.07 5448.64,1713.52 5452.9,1717.78 5454.97,1719.85 5461.72,1719.85 5481.06,1739.18 5481.06,1896.37 5494.53,1909.85 5506.08,1909.85 5519.56,1896.37 5519.56,1739.18 5538.89,1719.85 5576.43,1719.85 5583.12,1713.16 5586.11,1710.16 5593.88,1702.39 5604.69,1702.39 5607.27,1699.81 5618,1699.81 5620.58,1702.39 5631.32,1702.39 5633.9,1699.81 5644.64,1699.81 5647.22,1702.39 5657.96,1702.39 5660.54,1699.81 5671.27,1699.81 5673.85,1702.39 5684.59,1702.39 5687.17,1699.81 5697.91,1699.81 5700.49,1702.39 5711.23,1702.39 5713.81,1699.81 5724.55,1699.81 5727.13,1702.39 5737.86,1702.39 5740.44,1699.81 5751.18,1699.81 5753.76,1702.39 5764.5,1702.39 5767.08,1699.81 5777.82,1699.81 5780.4,1702.39 5809.24,1702.39 5811.42,1700.22 v1(5811.42,1682.27)
  L12 SIGNAL w4: v1(4988.98,1515.75) 5003.98,1500.75 5027.18,1500.75
LVDSB10_P: J29.F13 U1.D4 | length 1546.2
  L12 SIGNAL w3.5: 5026.18,1531.75 5037.68,1520.25 5052.96,1520.25 5120.78,1588.07 ; 5120.78,1588.07 5135.65,1602.94 5214.08,1602.94 5226.99,1590.02 5242.56,1590.02 5249.9,1597.35 5249.9,1605.09 5242.56,1612.42 5227.09,1627.9 5227.09,1650.4 5241.11,1664.43 5268.46,1664.43 5322.95,1609.93 5342.01,1609.93 5350.18,1618.09 5350.18,1637.15 5320.24,1667.09 5320.24,1694.43 5334.26,1708.46 5361.6,1708.46 5385.99,1684.07 5405.05,1684.07 5450.83,1729.85 5452.9,1729.85 5457.58,1729.85 5471.06,1743.32 5471.06,1900.51 5490.39,1919.85 5510.22,1919.85 5529.56,1900.51 5529.56,1743.32 5543.03,1729.85 5580.57,1729.85 5590.19,1720.23 5598.02,1712.39 5604.69,1712.39 5633.94,1712.39 5634.06,1712.27 5809.37,1712.27 5811.42,1714.32 v1(5811.42,1732.27)
  L12 SIGNAL w4: v1(4957.48,1515.75) 4960.54,1518.81 4967.76,1518.81 4980.7,1531.75 5026.18,1531.75
LVDSB11_N: J29.K8 U1.G3 | length 1067.5
  L7 SIGNAL w3.5: 4847.54,1610.9 4847.54,1615.05 4836.9,1625.7 4836.9,1629.97 4847.55,1640.63 4857.84,1640.63 4884.64,1667.43 4884.64,1712.5 4898.34,1726.2 4900.04,1727.9 4922.12,1727.9 4969.45,1775.24 5008.63,1814.41 5058.64,1814.41 5246.49,2002.27 5609.37,2002.27 5611.42,2000.22 v1(5611.42,1982.27)
  L7 SIGNAL w4: 4847.54,1610.9 4847.54,1562.69 v1(4862.99,1547.24)
LVDSB11_P: J29.K7 U1.H3 | length 1084
  L7 SIGNAL w3.5: 4816.25,1613.93 4816.25,1615.85 4826.9,1626.5 4826.9,1634.11 4843.41,1650.63 4853.7,1650.63 4874.64,1671.57 4874.64,1716.64 4888.34,1730.34 4895.9,1737.9 4917.97,1737.9 4959.45,1779.38 5004.49,1824.41 5054.49,1824.41 5242.35,2012.27 5609.37,2012.27 5611.42,2014.32 v1(5611.42,2032.27)
  L7 SIGNAL w4: 4816.25,1613.93 4816.25,1562.49 v1(4831.5,1547.24)
LVDSB12_N: J29.K14 U1.E3 | length 1490.5
  L10 SIGNAL w3.5: 5026.18,1531.24 5037.18,1542.24 5109.39,1542.24 5135.63,1568.49 5135.63,1619.49 5108.22,1646.89 5070.44,1684.67 5070.44,1732.17 5100.01,1761.73 5119.06,1761.73 5157.52,1723.27 5184.86,1723.27 5198.89,1737.3 5198.89,1764.64 5156.53,1806.99 5156.53,1826.05 5164.7,1834.22 5183.76,1834.22 5229.02,1788.95 5256.37,1788.95 5270.39,1802.98 5270.39,1830.32 5229.02,1871.69 5229.02,1890.75 5238.49,1900.22 5249.23,1900.22 5251.81,1897.64 5262.54,1897.64 5265.12,1900.22 5282.18,1900.22 5289.77,1892.63 5289.77,1888.98 5297.36,1881.38 5301.01,1881.38 5308.6,1873.79 5308.6,1870.14 5316.2,1862.55 5319.85,1862.55 5327.44,1854.96 5327.44,1851.31 5335.03,1843.72 5338.68,1843.72 5352.8,1829.59 5357.38,1829.59 5359.96,1827.01 5370.69,1827.01 5373.27,1829.59 5384.01,1829.59 5386.59,1827.01 5397.33,1827.01 5399.91,1829.59 5410.65,1829.59 5413.23,1827.01 5423.97,1827.01 5426.55,1829.59 5437.28,1829.59 5439.86,1827.01 5450.6,1827.01 5453.18,1829.59 5463.92,1829.59 5466.5,1827.01 5477.24,1827.01 5479.82,1829.59 5490.55,1829.59 5493.13,1827.01 5503.87,1827.01 5506.45,1829.59 5517.19,1829.59 5522.32,1824.47 5534.51,1812.27 5547,1799.78 5547,1724.3 5569.04,1702.27 5609.37,1702.27 5611.42,1700.22 v1(5611.42,1682.27)
  L10 SIGNAL w4: v1(4925.98,1547.24) 4941.98,1531.24 5026.18,1531.24
LVDSB12_P: J29.K13 U1.F3 | length 1500.6
  L10 SIGNAL w3.5: 5026.18,1563.24 5037.18,1552.24 5105.24,1552.24 5125.63,1572.63 5125.63,1615.35 5104.08,1636.89 5060.44,1680.53 5060.44,1736.31 5095.86,1771.73 5123.2,1771.73 5161.67,1733.27 5180.72,1733.27 5188.89,1741.44 5188.89,1760.5 5146.53,1802.85 5146.53,1830.19 5160.56,1844.22 5187.9,1844.22 5233.17,1798.95 5252.22,1798.95 5260.39,1807.12 5260.39,1826.17 5219.02,1867.55 5219.02,1894.89 5225.25,1901.13 5234.35,1910.22 5286.32,1910.22 5323.45,1873.09 5356.95,1839.59 5521.33,1839.59 5532.32,1828.61 5541.58,1819.34 5557,1803.92 5557,1728.45 5573.18,1712.27 5609.37,1712.27 5611.42,1714.32 v1(5611.42,1732.27)
  L10 SIGNAL w4: v1(4894.49,1547.24) 4897.47,1550.23 4906.34,1550.23 4919.36,1563.24 5026.18,1563.24
LVDSB13_N: J29.J10 U1.C3 | length 1666.1
  L7 SIGNAL w3.5: 5005.47,1614.6 4994.83,1625.24 4994.83,1636.41 5018.32,1659.9 5089.01,1659.9 5114.38,1685.27 5114.38,1739.05 5157.23,1781.9 5166.34,1791.01 5240.11,1791.01 5261.45,1769.67 5261.45,1678.78 5280.32,1659.9 5310.54,1629.68 5347.71,1629.68 5350.29,1627.1 5361.03,1627.1 5363.61,1629.68 5377.67,1629.68 5380.25,1627.1 5390.99,1627.1 5393.57,1629.68 5407.63,1629.68 5410.21,1627.1 5420.94,1627.1 5423.52,1629.68 5437.58,1629.68 5440.16,1627.1 5450.9,1627.1 5453.48,1629.68 5502.39,1629.68 5516.08,1643.37 5516.08,1647.51 5516.08,1656.52 5516.08,1665.34 5496.74,1684.68 5422.12,1684.68 5408.65,1698.15 5408.65,1709.7 5422.12,1723.18 5522.41,1723.18 5541.74,1742.51 5541.74,1762.34 5522.41,1781.68 5425.6,1781.68 5412.13,1795.15 5412.13,1806.7 5425.6,1820.18 5496.74,1820.18 5516.08,1839.51 5516.08,1882.12 5516.08,1892.72 5525.62,1902.27 5659.37,1902.27 5661.42,1900.22 v1(5661.42,1882.27)
  L7 SIGNAL w4: v1(4988.98,1547.24) 4992.04,1550.31 4992.04,1558.72 5005.47,1572.15 5005.47,1614.6
LVDSB13_P: J29.J9 U1.D3 | length 1674.2
  L7 SIGNAL w3.5: 4973.98,1616.1 4984.83,1626.95 4984.83,1640.55 5014.18,1669.9 5084.87,1669.9 5104.38,1689.41 5104.38,1743.19 5147.23,1786.05 5162.2,1801.01 5244.25,1801.01 5268.52,1776.74 5271.45,1773.81 5271.45,1682.92 5287.39,1666.97 5314.69,1639.68 5498.25,1639.68 5506.08,1647.51 5506.08,1656.52 5506.08,1661.2 5492.6,1674.68 5417.98,1674.68 5398.65,1694.01 5398.65,1713.84 5417.98,1733.18 5518.27,1733.18 5531.74,1746.65 5531.74,1758.2 5518.27,1771.68 5421.46,1771.68 5402.13,1791.01 5402.13,1810.84 5421.46,1830.18 5492.6,1830.18 5506.08,1843.65 5506.08,1882.12 5506.08,1896.86 5521.48,1912.27 5659.37,1912.27 5661.42,1914.32 v1(5661.42,1932.27)
  L7 SIGNAL w4: v1(4957.48,1547.24) 4973.98,1563.74 4973.98,1616.1
LVDSB14_N: J29.J7 U1.G2 | length 1596.6
  L10 SIGNAL w3.5: 4846.99,1617.09 4836.24,1627.84 4836.24,1650.72 4818.52,1668.44 4818.52,1689.38 4845.26,1716.12 4853.69,1716.12 4892.26,1754.69 4892.26,1832.27 4934.26,1874.27 4948.32,1874.27 4950.9,1871.69 4961.64,1871.69 4964.22,1874.27 4974.95,1874.27 4977.53,1871.69 4988.27,1871.69 4990.85,1874.27 5001.59,1874.27 5004.17,1871.69 5014.91,1871.69 5017.49,1874.27 5046.07,1874.27 5099.93,1928.13 5099.93,1961.65 5141.84,2003.56 5168,2003.56 5216.71,2052.27 5239.84,2052.27 5242.42,2049.69 5253.16,2049.69 5255.74,2052.27 5266.48,2052.27 5269.06,2049.69 5279.8,2049.69 5282.38,2052.27 5287.87,2052.27 5301.35,2038.79 5301.35,2001.92 5320.68,1982.59 5340.51,1982.59 5359.85,2001.92 5359.85,2057.2 5373.32,2070.68 5384.87,2070.68 5398.35,2057.2 5398.35,2007.68 5417.68,1988.35 5437.51,1988.35 5456.85,2007.68 5456.85,2057.2 5470.32,2070.68 5481.87,2070.68 5495.35,2057.2 5495.35,1997.68 5514.68,1978.35 5534.51,1978.35 5553.85,1997.68 5553.85,2038.79 5567.32,2052.27 5581.38,2052.27 5583.96,2049.69 5594.7,2049.69 5597.28,2052.27 5608.02,2052.27 5610.6,2049.69 5621.33,2049.69 5623.91,2052.27 5634.65,2052.27 5637.23,2049.69 5647.97,2049.69 5650.55,2052.27 5659.37,2052.27 5661.42,2050.22 v1(5661.42,2032.27)
  L10 SIGNAL w4: 4846.99,1617.09 4846.99,1594.74 v1(4862.99,1578.74)
LVDSB14_P: J29.J6 U1.H2 | length 1596.1
  L10 SIGNAL w3.5: 4815.5,1617.09 4826.24,1627.84 4826.24,1646.58 4818.67,1654.15 4808.52,1664.3 4808.52,1693.52 4841.12,1726.12 4849.54,1726.12 4882.26,1758.83 4882.26,1836.41 4930.12,1884.27 5041.93,1884.27 5089.93,1932.27 5089.93,1965.79 5137.69,2013.56 5163.86,2013.56 5212.57,2062.27 5292.01,2062.27 5311.35,2042.94 5311.35,2006.07 5324.82,1992.59 5336.37,1992.59 5349.85,2006.07 5349.85,2061.34 5369.18,2080.68 5389.01,2080.68 5408.35,2061.34 5408.35,2011.82 5421.82,1998.35 5433.37,1998.35 5446.85,2011.82 5446.85,2061.34 5466.18,2080.68 5486.01,2080.68 5505.35,2061.34 5505.35,2001.82 5518.82,1988.35 5530.37,1988.35 5543.85,2001.82 5543.85,2042.94 5563.18,2062.27 5659.37,2062.27 5661.42,2064.32 v1(5661.42,2082.27)
  L10 SIGNAL w4: 4815.5,1617.09 4815.5,1594.74 v1(4831.5,1578.74)
LVDSB15_N: J29.J12 U1.E2 | length 1592.1
  L12 SIGNAL w3.5: 5025.69,1595.24 5037.18,1583.74 5059.29,1583.74 5118.18,1642.63 5127.41,1651.86 5127.41,1704.82 5152.44,1729.85 5200.48,1729.85 5227.82,1729.85 5235.43,1722.24 5254.49,1722.24 5262.65,1730.4 5262.65,1749.46 5247.04,1765.07 5247.04,1792.41 5261.07,1806.44 5288.41,1806.44 5332.58,1762.26 5351.64,1762.26 5359.8,1770.43 5359.8,1789.49 5315.63,1833.66 5315.63,1861 5329.66,1875.03 5357,1875.03 5401.17,1830.85 5420.23,1830.85 5428.39,1839.02 5428.39,1858.08 5392.22,1894.25 5392.22,1921.59 5398.46,1927.83 5406.05,1935.42 5406.05,1939.07 5413.64,1946.66 5417.29,1946.66 5424.89,1954.26 5424.89,1957.9 5432.48,1965.5 5436.13,1965.5 5443.72,1973.09 5443.72,1976.74 5451.31,1984.33 5454.96,1984.33 5462.55,1991.92 5462.55,1995.57 5470.15,2003.16 5473.8,2003.16 5481.39,2010.76 5481.39,2014.41 5488.98,2022 5492.63,2022 5493.79,2023.16 5541.39,2023.16 5565.61,1998.94 5565.61,1988.2 5568.19,1985.62 5568.19,1974.88 5565.61,1972.3 5565.61,1961.57 5568.19,1958.99 5568.19,1948.25 5565.61,1945.67 5565.61,1934.93 5568.19,1932.35 5568.19,1921.61 5565.61,1919.03 5565.61,1908.3 5568.19,1905.72 5568.19,1894.98 5565.61,1892.4 5565.61,1881.66 5568.19,1879.08 5568.19,1868.34 5565.61,1865.76 5565.61,1855.02 5568.19,1852.44 5568.19,1841.71 5565.61,1839.13 5565.61,1828.39 5568.19,1825.81 5568.19,1815.07 5565.61,1812.49 5565.61,1790.08 5593.42,1762.27 5604.15,1762.27 5606.73,1764.85 5617.47,1764.85 5620.05,1762.27 5630.79,1762.27 5633.37,1764.85 5644.11,1764.85 5646.69,1762.27 5659.37,1762.27 5661.42,1764.32 v1(5661.42,1782.27)
  L12 SIGNAL w4: v1(4925.98,1578.74) 4942.48,1595.24 5025.69,1595.24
